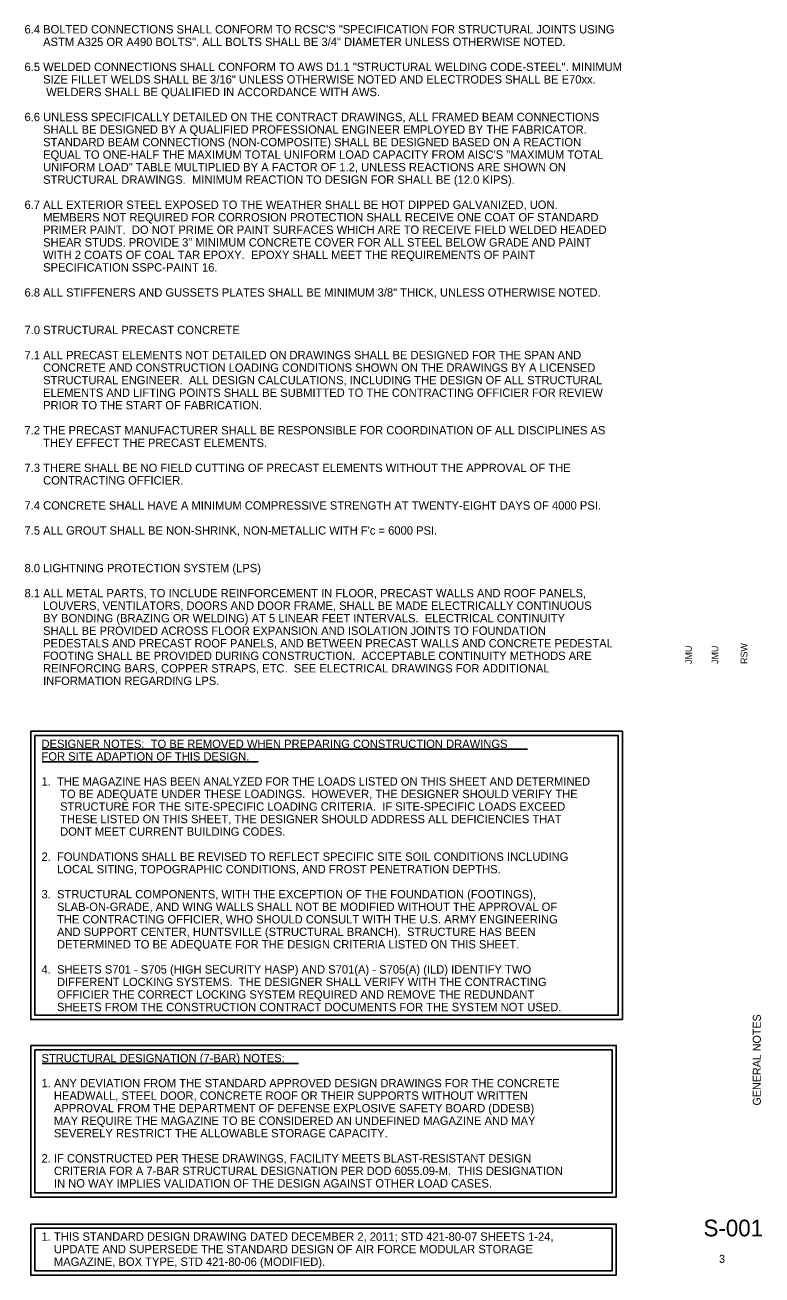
# Model space of a CAD drawing. Extents: x 0.17 to 2.69, y 0.12 to 1.68.
# Drawn here: x 1.771 to 2.69, y 0.123 to 1.682 of the extents above; entities that cross this region are included whole.
import ezdxf

# ---------------------------------------------------------------- set-up
doc = ezdxf.new("R2010")
doc.units = 0
doc.layers.add('G-ANNO-TEXT', color=7, linetype='Continuous')
doc.layers.add('G-ANNO-TTLB', color=7, linetype='Continuous')

msp = doc.modelspace()

# ---------------------------------------------------------------- linework, layer by layer
at = {"layer": 'G-ANNO-TEXT'}
for p, q in [((1.7925, 0.7787), (2.3978, 0.7787)), ((1.7925, 0.7631), (2.062, 0.7631)), ((1.7925, 0.3869), (2.1125, 0.3869))]:
    msp.add_line(p, q, dxfattribs=at)
for points in [[(1.7783, 0.8011), (2.5164, 0.8011), (2.5164, 0.4418), (1.7783, 0.4418)], [(1.7835, 0.7959), (2.5112, 0.7959), (2.5112, 0.447), (1.7835, 0.447)], [(1.7783, 0.4093), (2.5086, 0.4093), (2.5086, 0.2201), (1.7783, 0.2201)], [(1.7835, 0.404), (2.5034, 0.404), (2.5034, 0.2253), (1.7835, 0.2253)], [(1.7783, 0.1866), (2.5086, 0.1866), (2.5086, 0.123), (1.7783, 0.123)], [(1.7835, 0.1814), (2.5034, 0.1814), (2.5034, 0.1282), (1.7835, 0.1282)]]:
    msp.add_lwpolyline(points, close=True, dxfattribs=at)

# ---------------------------------------------------------------- texts
for s, p in [('6.4 BOLTED CONNECTIONS SHALL CONFORM TO RCSC\'S "SPECIFICATION FOR STRUCTURAL JOINTS USING', (1.7706, 1.6713)), ('      ASTM A325 OR A490 BOLTS". ALL BOLTS SHALL BE 3/4" DIAMETER UNLESS OTHERWISE NOTED.', (1.7706, 1.6556)), ('6.5 WELDED CONNECTIONS SHALL CONFORM TO AWS D1.1 "STRUCTURAL WELDING CODE-STEEL". MINIMUM', (1.7706, 1.6244)), ('      SIZE FILLET WELDS SHALL BE 3/16" UNLESS OTHERWISE NOTED AND ELECTRODES SHALL BE E70xx. ', (1.7706, 1.6088)), ('       WELDERS SHALL BE QUALIFIED IN ACCORDANCE WITH AWS.', (1.7706, 1.5931)), ('6.6 UNLESS SPECIFICALLY DETAILED ON THE CONTRACT DRAWINGS, ALL FRAMED BEAM CONNECTIONS ', (1.7706, 1.5619)), ('      SHALL BE DESIGNED BY A QUALIFIED PROFESSIONAL ENGINEER EMPLOYED BY THE FABRICATOR.', (1.7706, 1.5463)), ('      STANDARD BEAM CONNECTIONS (NON-COMPOSITE) SHALL BE DESIGNED BASED ON A REACTION ', (1.7706, 1.5306)), ('      EQUAL TO ONE-HALF THE MAXIMUM TOTAL UNIFORM LOAD CAPACITY FROM AISC\'S "MAXIMUM TOTAL', (1.7706, 1.515)), ('      UNIFORM LOAD" TABLE MULTIPLIED BY A FACTOR OF 1.2, UNLESS REACTIONS ARE SHOWN ON ', (1.7706, 1.4994)), ('      STRUCTURAL DRAWINGS.  MINIMUM REACTION TO DESIGN FOR SHALL BE (12.0 KIPS). ', (1.7706, 1.4838)), ('6.7 ALL EXTERIOR STEEL EXPOSED TO THE WEATHER SHALL BE HOT DIPPED GALVANIZED, UON. ', (1.7706, 1.4525)), ('      MEMBERS NOT REQUIRED FOR CORROSION PROTECTION SHALL RECEIVE ONE COAT OF STANDARD ', (1.7706, 1.4369)), ('      PRIMER PAINT.  DO NOT PRIME OR PAINT SURFACES WHICH ARE TO RECEIVE FIELD WELDED HEADED ', (1.7706, 1.4213)), ('      SHEAR STUDS. PROVIDE 3" MINIMUM CONCRETE COVER FOR ALL STEEL BELOW GRADE AND PAINT ', (1.7706, 1.4056)), ('      WITH 2 COATS OF COAL TAR EPOXY.  EPOXY SHALL MEET THE REQUIREMENTS OF PAINT ', (1.7706, 1.39)), ('      SPECIFICATION SSPC-PAINT 16.   ', (1.7706, 1.3744)), ('6.8 ALL STIFFENERS AND GUSSETS PLATES SHALL BE MINIMUM 3/8" THICK, UNLESS OTHERWISE NOTED. ', (1.7706, 1.3431)), ('7.0 STRUCTURAL PRECAST CONCRETE', (1.7706, 1.2963)), ('7.1 ALL PRECAST ELEMENTS NOT DETAILED ON DRAWINGS SHALL BE DESIGNED FOR THE SPAN AND', (1.7706, 1.265)), ('      CONCRETE AND CONSTRUCTION LOADING CONDITIONS SHOWN ON THE DRAWINGS BY A LICENSED', (1.7706, 1.2494)), ('      STRUCTURAL ENGINEER.  ALL DESIGN CALCULATIONS, INCLUDING THE DESIGN OF ALL STRUCTURAL', (1.7706, 1.2338)), ('      ELEMENTS AND LIFTING POINTS SHALL BE SUBMITTED TO THE CONTRACTING OFFICIER FOR REVIEW', (1.7706, 1.2181)), ('      PRIOR TO THE START OF FABRICATION.', (1.7706, 1.2025)), ('7.2 THE PRECAST MANUFACTURER SHALL BE RESPONSIBLE FOR COORDINATION OF ALL DISCIPLINES AS', (1.7706, 1.1713)), ('      THEY EFFECT THE PRECAST ELEMENTS.', (1.7706, 1.1556)), ('7.3 THERE SHALL BE NO FIELD CUTTING OF PRECAST ELEMENTS WITHOUT THE APPROVAL OF THE', (1.7706, 1.1244)), ('      CONTRACTING OFFICIER.', (1.7706, 1.1088)), ('7.4 CONCRETE SHALL HAVE A MINIMUM COMPRESSIVE STRENGTH AT TWENTY-EIGHT DAYS OF 4000 PSI.', (1.7706, 1.0775)), ("7.5 ALL GROUT SHALL BE NON-SHRINK, NON-METALLIC WITH F'c = 6000 PSI.", (1.7706, 1.0463)), ('8.0 LIGHTNING PROTECTION SYSTEM (LPS)', (1.7706, 0.9994)), ('8.1 ALL METAL PARTS, TO INCLUDE REINFORCEMENT IN FLOOR, PRECAST WALLS AND ROOF PANELS,', (1.7706, 0.9681)), ('      LOUVERS, VENTILATORS, DOORS AND DOOR FRAME, SHALL BE MADE ELECTRICALLY CONTINUOUS', (1.7706, 0.9525)), ('      BY BONDING (BRAZING OR WELDING) AT 5 LINEAR FEET INTERVALS.  ELECTRICAL CONTINUITY', (1.7706, 0.9369)), ('      SHALL BE PROVIDED ACROSS FLOOR EXPANSION AND ISOLATION JOINTS TO FOUNDATION', (1.7706, 0.9213)), ('      PEDESTALS AND PRECAST ROOF PANELS, AND BETWEEN PRECAST WALLS AND CONCRETE PEDESTAL', (1.7706, 0.9056)), ('      FOOTING SHALL BE PROVIDED DURING CONSTRUCTION.  ACCEPTABLE CONTINUITY METHODS ARE', (1.7706, 0.89)), ('      REINFORCING BARS, COPPER STRAPS, ETC.  SEE ELECTRICAL DRAWINGS FOR ADDITIONAL', (1.7706, 0.8744)), ('      INFORMATION REGARDING LPS.', (1.7706, 0.8588)), ('DESIGNER NOTES:  TO BE REMOVED WHEN PREPARING CONSTRUCTION DRAWINGS ', (1.7918, 0.7802)), ('FOR SITE ADAPTION OF THIS DESIGN.', (1.7918, 0.7645)), ('1.  THE MAGAZINE HAS BEEN ANALYZED FOR THE LOADS LISTED ON THIS SHEET AND DETERMINED', (1.7918, 0.7333)), ('      TO BE ADEQUATE UNDER THESE LOADINGS.  HOWEVER, THE DESIGNER SHOULD VERIFY THE ', (1.7918, 0.7177)), ('      STRUCTURE FOR THE SITE-SPECIFIC LOADING CRITERIA.  IF SITE-SPECIFIC LOADS EXCEED ', (1.7918, 0.702)), ('      THESE LISTED ON THIS SHEET, THE DESIGNER SHOULD ADDRESS ALL DEFICIENCIES THAT', (1.7918, 0.6864)), ('      DONT MEET CURRENT BUILDING CODES.', (1.7918, 0.6708)), ('2.  FOUNDATIONS SHALL BE REVISED TO REFLECT SPECIFIC SITE SOIL CONDITIONS INCLUDING', (1.7918, 0.6395)), ('     LOCAL SITING, TOPOGRAPHIC CONDITIONS, AND FROST PENETRATION DEPTHS.', (1.7918, 0.6239)), ('3.  STRUCTURAL COMPONENTS, WITH THE EXCEPTION OF THE FOUNDATION (FOOTINGS),', (1.7918, 0.5927)), ('     SLAB-ON-GRADE, AND WING WALLS SHALL NOT BE MODIFIED WITHOUT THE APPROVAL OF', (1.7918, 0.577)), ('     THE CONTRACTING OFFICIER, WHO SHOULD CONSULT WITH THE U.S. ARMY ENGINEERING', (1.7918, 0.5614)), ('     AND SUPPORT CENTER, HUNTSVILLE (STRUCTURAL BRANCH).  STRUCTURE HAS BEEN', (1.7918, 0.5458)), ('     DETERMINED TO BE ADEQUATE FOR THE DESIGN CRITERIA LISTED ON THIS SHEET.  ', (1.7918, 0.5302)), ('4.  SHEETS S701 - S705 (HIGH SECURITY HASP) AND S701(A) - S705(A) (ILD) IDENTIFY TWO', (1.7918, 0.4989)), ('     DIFFERENT LOCKING SYSTEMS.  THE DESIGNER SHALL VERIFY WITH THE CONTRACTING', (1.7918, 0.4833)), ('     OFFICIER THE CORRECT LOCKING SYSTEM REQUIRED AND REMOVE THE REDUNDANT ', (1.7918, 0.4677)), ('     SHEETS FROM THE CONSTRUCTION CONTRACT DOCUMENTS FOR THE SYSTEM NOT USED.', (1.7918, 0.452)), ('STRUCTURAL DESIGNATION (7-BAR) NOTES:', (1.7918, 0.3883)), ('1. ANY DEVIATION FROM THE STANDARD APPROVED DESIGN DRAWINGS FOR THE CONCRETE', (1.7918, 0.3571)), ('    HEADWALL, STEEL DOOR, CONCRETE ROOF OR THEIR SUPPORTS WITHOUT WRITTEN ', (1.7918, 0.3415)), ('    APPROVAL FROM THE DEPARTMENT OF DEFENSE EXPLOSIVE SAFETY BOARD (DDESB)', (1.7918, 0.3258)), ('    MAY REQUIRE THE MAGAZINE TO BE CONSIDERED AN UNDEFINED MAGAZINE AND MAY ', (1.7918, 0.3102)), ('    SEVERELY RESTRICT THE ALLOWABLE STORAGE CAPACITY.', (1.7918, 0.2946)), ('2. IF CONSTRUCTED PER THESE DRAWINGS, FACILITY MEETS BLAST-RESISTANT DESIGN', (1.7918, 0.2633)), ('    CRITERIA FOR A 7-BAR STRUCTURAL DESIGNATION PER DOD 6055.09-M.  THIS DESIGNATION', (1.7918, 0.2477)), ('    IN NO WAY IMPLIES VALIDATION OF THE DESIGN AGAINST OTHER LOAD CASES.', (1.7918, 0.2321)), ('1. THIS STANDARD DESIGN DRAWING DATED DECEMBER 2, 2011; STD 421-80-07 SHEETS 1-24, ', (1.7918, 0.1657)), ('    UPDATE AND SUPERSEDE THE STANDARD DESIGN OF AIR FORCE MODULAR STORAGE', (1.7918, 0.1501)), ('    MAGAZINE, BOX TYPE, STD 421-80-06 (MODIFIED).', (1.7918, 0.1344))]:
    msp.add_text(s, height=0.010417, dxfattribs=at).set_placement(p)
at = {"layer": 'G-ANNO-TTLB'}
for s, height, p in [('JMU', 0.00833, (2.603, 0.885)), ('JMU', 0.00833, (2.6359, 0.885)), ('RSW', 0.00833, (2.6722, 0.885)), ('GENERAL NOTES', 0.01, (2.689, 0.3344))]:
    msp.add_text(s, height=height, rotation=90, dxfattribs=at).set_placement(p)
for s, height, p in [('S-001', 0.02083, (2.6175, 0.1712)), ('3', 0.01, (2.6369, 0.1382))]:
    msp.add_text(s, height=height, dxfattribs=at).set_placement(p)

doc.saveas('drawing.dxf')
